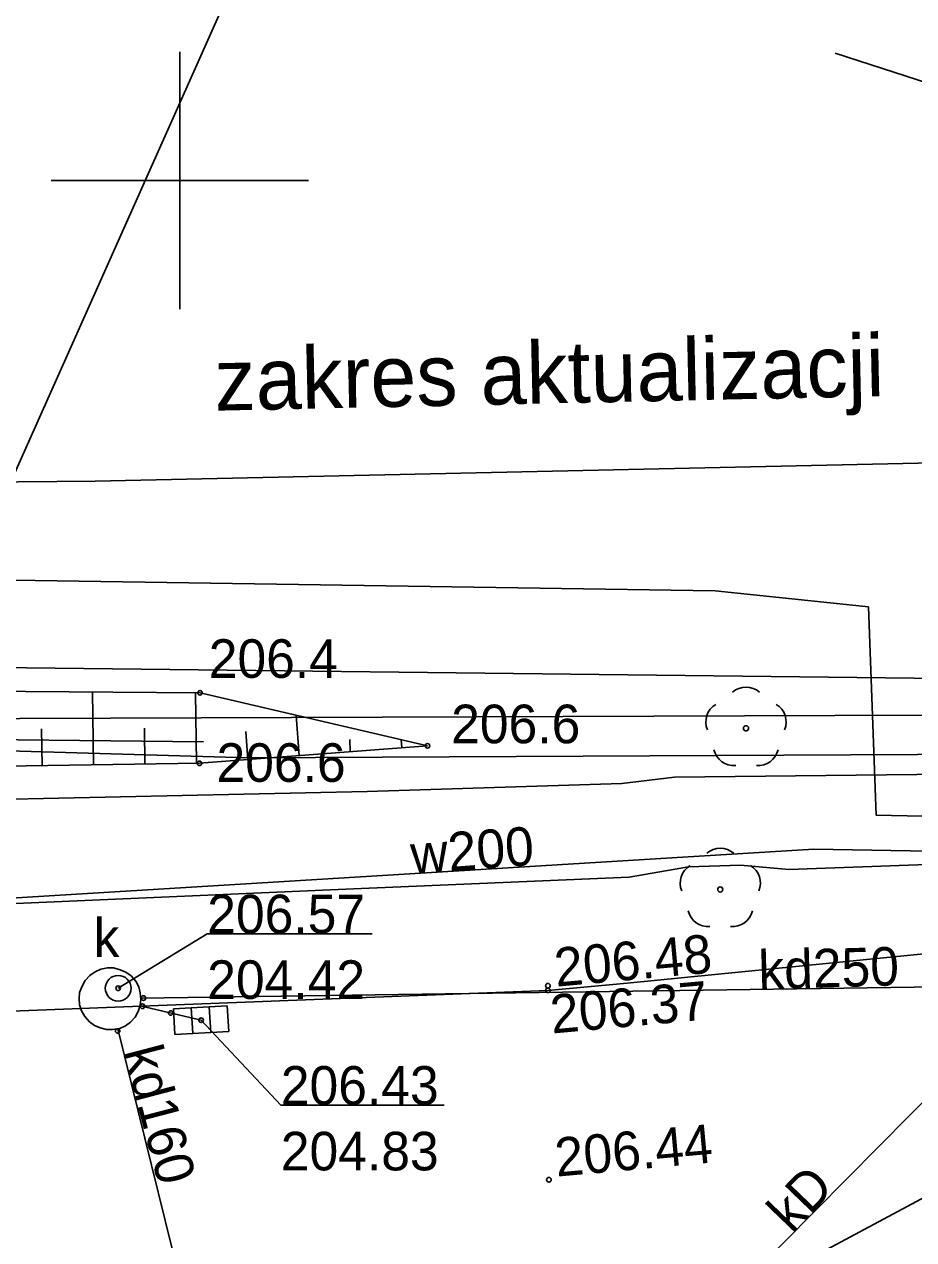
# Model space of a CAD drawing. Extents: x 6512606 to 6513347, y 6022524 to 6022728.
# Drawn here: x 6512746.98 to 6512764.26, y 6022679.43 to 6022703.04 of the extents above; entities that cross this region are included whole.
import ezdxf

# ---------------------------------------------------------------- set-up
doc = ezdxf.new("R2010")
doc.units = 0
for name, color, linetype in [('218-kontur użytku gruntowego', 7, 'Continuous'), ('219-działka ewidencyjna', 7, 'Continuous'), ('4', 7, 'Continuous'), ('820-Skarpa nieumocniona', 7, 'Continuous'), ('823-Szczyt skarpy nieumocninej', 7, 'Continuous'), ('824-Podnóże skarpy nieumocninej', 7, 'Continuous'), ('903-Żywopłot', 7, 'Continuous'), ('996-Tekst dodatkowy mały', 7, 'Continuous'), ('chodnik (powierzchnia)', 7, 'Continuous'), ('Default', 7, 'Continuous'), ('drzewo liściaste (punkt)', 7, 'Continuous'), ('jezdnia (powierzchnia)', 7, 'Continuous'), ('komora podziemna - przewód kanalizacyjny (powierzchnia)', 7, 'Continuous'), ('kratka ściekowa (punkt)', 7, 'Continuous'), ('krawężnik (linia)', 7, 'Continuous'), ('maxp_opisy', 7, 'Continuous'), ('Obszar opracowania', 7, 'Continuous'), ('przewód elektroenergetyczny niskiego napięcia (linia)', 7, 'Continuous'), ('przewód gazowy (linia)', 7, 'Continuous'), ('przewód kanalizacyjny (linia)', 7, 'Continuous'), ('przewód kanalizacyjny (linia)-Atr1', 7, 'Continuous'), ('przewód telekomunikacyjny (linia)', 7, 'Continuous'), ('przewód wodociągowy (linia)', 7, 'Continuous'), ('przewód wodociągowy (linia)-Atr1', 7, 'Continuous'), ('punkt o określonej wysokości (sieć kanalizacyjna)', 7, 'Continuous'), ('punkt o określonej wysokości (sieć kanalizacyjna)-Atr2', 7, 'Continuous'), ('punkt o określonej wysokości (sieć kanalizacyjna)-Atr3', 7, 'Continuous'), ('punkt wysokościowy naturalny', 7, 'Continuous'), ('punkt wysokościowy naturalny-Atr2', 7, 'Continuous'), ('punkt wysokościowy sztuczny', 7, 'Continuous'), ('punkt wysokościowy sztuczny-Atr2', 7, 'Continuous'), ('właz okrągły - siec kanalizacyjna (punkt)', 7, 'Continuous'), ('właz okrągły - siec kanalizacyjna (punkt)-Atr17', 7, 'Continuous')]:
    doc.layers.add(name, color=color, linetype=linetype)

# ---------------------------------------------------------------- blocks, each defined once
blk = doc.blocks.new('PW01')
at = {"layer": 'Default'}
blk.add_circle((0, 0), 0.45, dxfattribs=at)
blk = doc.blocks.new('OP021')
at = {"layer": 'Default'}
blk.add_circle((0, 0), 0.5, dxfattribs=at)
for centre, start, end in [((0, 4), 49.272, 130.728), ((-3.8, 1.24), 121.308, 202.548), ((3.8, 1.24), 337.452, 58.692), ((-2.35, -3.24), 193.221, 274.871), ((2.35, -3.24), 265.129, 346.779)]:
    blk.add_arc(centre, 4, start, end, dxfattribs=at)
blk = doc.blocks.new('US22')
at = {"layer": 'Default'}
blk.add_circle((0, 0), 2.5, dxfattribs=at)
blk = doc.blocks.new('US05')
at = {"layer": 'Default'}
for p, q in [((-5.25, -2.5), (-5.25, 2.5)), ((-5.25, 2.5), (-1.75, 2.5)), ((-1.75, -2.5), (-1.75, 2.5)), ((-1.75, 2.5), (1.75, 2.5)), ((1.75, -2.5), (1.75, 2.5)), ((1.75, 2.5), (5.25, 2.5)), ((5.25, -2.5), (5.25, 2.5)), ((-5.25, -2.5), (-1.75, -2.5)), ((-1.75, -2.5), (1.75, -2.5)), ((1.75, -2.5), (5.25, -2.5))]:
    blk.add_line(p, q, dxfattribs=at)
blk = doc.blocks.new('PW02')
at = {"layer": 'Default'}
blk.add_circle((0, 0), 0.45, dxfattribs=at)

msp = doc.modelspace()

# ---------------------------------------------------------------- linework, layer by layer
at = {"layer": '218-kontur użytku gruntowego'}
for points in [[(6512706.4, 6022691.01), (6512787.08, 6022690.07)], [(6512787.08, 6022690.07), (6512706.4, 6022691.01)]]:
    msp.add_lwpolyline(points, dxfattribs=at)
at = {"layer": '219-działka ewidencyjna'}
msp.add_lwpolyline([(6512706.4, 6022691.01), (6512787.08, 6022690.07)], dxfattribs=at)
at = {"layer": '4'}
msp.add_lwpolyline([(6512706.4, 6022691.01), (6512787.08, 6022690.07)], dxfattribs=at)
at = {"layer": '820-Skarpa nieumocniona'}
for p, q in [((6512748.32, 6022688.65), (6512748.3, 6022690.07)), ((6512750.32, 6022688.68), (6512750.3, 6022690.05)), ((6512752.32, 6022688.83), (6512752.26, 6022689.61)), ((6512749.32, 6022688.66), (6512749.31, 6022689.36)), ((6512747.32, 6022688.63), (6512747.31, 6022689.35)), ((6512751.32, 6022688.75), (6512751.28, 6022689.3)), ((6512753.31, 6022688.91), (6512753.3, 6022689.14)), ((6512754.31, 6022688.98), (6512754.3, 6022689.14))]:
    msp.add_line(p, q, dxfattribs=at)
at = {"layer": '823-Szczyt skarpy nieumocninej'}
msp.add_lwpolyline([(6512754.81, 6022689.02), (6512750.38, 6022688.68), (6512731.85, 6022688.4), (6512721.27, 6022688.58), (6512714.51, 6022690.92)], dxfattribs=at)
at = {"layer": '824-Podnóże skarpy nieumocninej'}
msp.add_lwpolyline([(6512714.51, 6022690.92), (6512719.59, 6022690.77), (6512731.72, 6022690.19), (6512750.39, 6022690.05), (6512754.81, 6022689.02)], dxfattribs=at)
at = {"layer": '903-Żywopłot'}
msp.add_lwpolyline([(6512750.46, 6022689.1), (6512732.44, 6022689.29)], dxfattribs=at)
at = {"layer": 'chodnik (powierzchnia)'}
for points in [[(6512780.55, 6022688.53), (6512780.6, 6022690.36), (6512779.7, 6022699.13), (6512765.93, 6022701.44), (6512762.734, 6022702.478)], [(6512786.39, 6022689.96), (6512786.43, 6022689.56), (6512785.75, 6022688.59), (6512780.55, 6022688.53), (6512773.92, 6022688.46), (6512772.96, 6022688.47), (6512771.38, 6022688.54), (6512759.61, 6022688.41), (6512758.59, 6022688.29), (6512753.64, 6022688.13), (6512742.85, 6022687.9), (6512740.21, 6022687.75), (6512727.76, 6022687.39)], [(6512770.26, 6022685.56), (6512768.81, 6022686.87), (6512761.83, 6022686.62), (6512760.89, 6022686.7), (6512759.88, 6022686.67), (6512758.73, 6022686.47), (6512753.37, 6022686.24), (6512740.24, 6022685.67), (6512727.63, 6022685.27)]]:
    msp.add_lwpolyline(points, dxfattribs=at)
at = {"layer": 'Default'}
for p, q in [((6512750, 6022697.5), (6512750, 6022702.5)), ((6512747.5, 6022700), (6512752.5, 6022700))]:
    msp.add_line(p, q, dxfattribs=at)
at = {"layer": 'jezdnia (powierzchnia)'}
msp.add_lwpolyline([(6512707.74, 6022685), (6512715.41, 6022684.53), (6512729.72, 6022683.88), (6512743.02, 6022683.72), (6512757.15, 6022684.27)], dxfattribs=at)
at = {"layer": 'komora podziemna - przewód kanalizacyjny (powierzchnia)'}
msp.add_lwpolyline([(6512749.24, 6022684.1), (6512749.23, 6022683.98), (6512749.19, 6022683.86), (6512749.13, 6022683.75), (6512749.04, 6022683.65), (6512748.94, 6022683.58), (6512748.83, 6022683.53), (6512748.69, 6022683.51), (6512748.57, 6022683.51), (6512748.45, 6022683.54), (6512748.34, 6022683.59), (6512748.24, 6022683.66), (6512748.15, 6022683.76), (6512748.09, 6022683.87), (6512748.05, 6022683.99), (6512748.04, 6022684.11), (6512748.05, 6022684.23), (6512748.1, 6022684.35), (6512748.16, 6022684.46), (6512748.25, 6022684.56), (6512748.35, 6022684.63), (6512748.46, 6022684.68), (6512748.59, 6022684.71), (6512748.71, 6022684.71), (6512748.84, 6022684.67), (6512748.95, 6022684.62), (6512749.05, 6022684.55), (6512749.14, 6022684.45), (6512749.2, 6022684.34), (6512749.23, 6022684.22)], close=True, dxfattribs=at)
at = {"layer": 'krawężnik (linia)'}
for points in [[(6512757.15, 6022684.27), (6512758.69, 6022684.41), (6512769.83, 6022685.51), (6512772.56, 6022685.82), (6512777.4, 6022686.23), (6512782.53, 6022686.49), (6512786.32, 6022686.51), (6512790.79, 6022686.51)], [(6512757.15, 6022684.27), (6512743.02, 6022683.72), (6512729.72, 6022683.88), (6512715.41, 6022684.53), (6512707.74, 6022685)]]:
    msp.add_lwpolyline(points, dxfattribs=at)
at = {"layer": 'maxp_opisy'}
msp.add_lwpolyline([(6512737.272, 6022673), (6512753.512, 6022709.396), (6512783.273, 6022709.39)], dxfattribs=at)
at = {"layer": 'Obszar opracowania'}
msp.add_lwpolyline([(6512710.98, 6022693.84), (6512748.35, 6022694.16), (6512798.11, 6022695.25), (6512807.47, 6022695.46), (6512809.66, 6022606.87), (6512863.71, 6022622.03), (6512875.13, 6022581.36), (6512755.22, 6022535.25), (6512691.61, 6022568.03), (6512709.16, 6022605.16)], close=True, dxfattribs=at)
at = {"layer": 'przewód elektroenergetyczny niskiego napięcia (linia)'}
for points in [[(6512782.09, 6022689.68), (6512702.887, 6022689.392)], [(6512702.887, 6022689.392), (6512782.09, 6022689.68)], [(6512751.03, 6022673.06), (6512782.09, 6022689.68)], [(6512782.09, 6022689.68), (6512751.03, 6022673.06)]]:
    msp.add_lwpolyline(points, dxfattribs=at)
at = {"layer": 'przewód gazowy (linia)'}
msp.add_lwpolyline([(6512790.27, 6022690.86), (6512788.32, 6022687.6), (6512767.44, 6022687.59), (6512763.53, 6022687.67), (6512763.38, 6022691.72), (6512760.4, 6022692.03), (6512740.79, 6022692.33), (6512723.64, 6022692.06), (6512711.62, 6022691.95), (6512703.17, 6022690.39), (6512702.97, 6022685.4), (6512702.78, 6022684.183)], dxfattribs=at)
at = {"layer": 'przewód kanalizacyjny (linia)'}
for points in [[(6512749.24, 6022684.12), (6512782.48, 6022684.59)], [(6512756.19, 6022673.77), (6512766.65, 6022684.34)], [(6512749.23, 6022683.97), (6512750.41, 6022683.69)], [(6512750.37, 6022677.15), (6512748.79, 6022683.52)]]:
    msp.add_lwpolyline(points, dxfattribs=at)
at = {"layer": 'przewód telekomunikacyjny (linia)'}
msp.add_lwpolyline([(6512786.53, 6022688.5), (6512773.43, 6022688.9), (6512751.33, 6022688.79), (6512741.32, 6022689.08), (6512718.97, 6022688.75), (6512713.12, 6022690.07), (6512711.25, 6022690.1), (6512706.82, 6022689.08), (6512704.98, 6022689.07)], dxfattribs=at)
at = {"layer": 'przewód wodociągowy (linia)'}
msp.add_lwpolyline([(6512777.27, 6022686.75), (6512776.94, 6022686.76), (6512762.32, 6022687.01), (6512742.89, 6022685.83), (6512741.87, 6022684.29)], dxfattribs=at)
at = {"layer": 'punkt o określonej wysokości (sieć kanalizacyjna)-Atr2'}
for points in [[(6512748.8, 6022684.31), (6512750.53, 6022685.37), (6512753.734, 6022685.37)], [(6512750.41, 6022683.69), (6512751.96, 6022682.04), (6512755.133, 6022682.04)]]:
    msp.add_lwpolyline(points, dxfattribs=at)

# ---------------------------------------------------------------- block references
at = {"layer": 'drzewo liściaste (punkt)', "xscale": 0.1, "yscale": 0.10000000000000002}
for p in [(6512761, 6022689.36), (6512760.5, 6022686.23)]:
    msp.add_blockref('OP021', p, dxfattribs=at)
at = {"layer": 'kratka ściekowa (punkt)', "xscale": 0.1, "yscale": 0.09999999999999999, "rotation": 3.2700000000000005}
msp.add_blockref('US05', (6512750.41, 6022683.69), dxfattribs=at)
at = {"layer": 'punkt o określonej wysokości (sieć kanalizacyjna)', "xscale": 0.1, "yscale": 0.10000000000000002}
msp.add_blockref('PW01', (6512748.8, 6022684.31), dxfattribs=at)
at = {"layer": 'punkt o określonej wysokości (sieć kanalizacyjna)'}
for p, xscale, yscale, rotation in [((6512749.29, 6022684.12), 0.1, 0.10000000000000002, 1.62), ((6512749.27, 6022683.96), 0.10000000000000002, 0.1, -12.426), ((6512749.82, 6022683.83), 0.10000000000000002, 0.1, -12.426), ((6512750.41, 6022683.69), 0.1, 0.09999999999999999, 3.2700000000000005), ((6512748.79, 6022683.48), 0.1, 0.10000000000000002, -75.265)]:
    msp.add_blockref('PW01', p, dxfattribs=dict(at, xscale=xscale, yscale=yscale, rotation=rotation))
at = {"layer": 'punkt wysokościowy naturalny', "xscale": 0.1, "yscale": 0.10000000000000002}
for p in [(6512750.39, 6022690.05), (6512754.81, 6022689.02), (6512750.38, 6022688.68)]:
    msp.add_blockref('PW01', p, dxfattribs=at)
at = {"layer": 'punkt wysokościowy sztuczny', "xscale": 0.1, "yscale": 0.10000000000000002}
for p in [(6512757.15, 6022684.36), (6512757.15, 6022684.27), (6512757.17, 6022680.59)]:
    msp.add_blockref('PW02', p, dxfattribs=at)
at = {"layer": 'właz okrągły - siec kanalizacyjna (punkt)', "xscale": 0.1, "yscale": 0.10000000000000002}
msp.add_blockref('US22', (6512748.8, 6022684.31), dxfattribs=at)

# ---------------------------------------------------------------- texts
at = {"layer": '996-Tekst dodatkowy mały'}
msp.add_text('zakres aktualizacji', height=1.2, rotation=1.255, dxfattribs=at).set_placement((6512750.68, 6022695.53))
at = {"layer": 'przewód kanalizacyjny (linia)-Atr1'}
for s, rotation, p in [('kd250', 1.631, (6512761.25, 6022684.29)), ('kd160', 284.715, (6512748.9, 6022683.09)), ('kD', 46.112, (6512761.89, 6022679.53))]:
    msp.add_text(s, height=0.75, rotation=rotation, dxfattribs=at).set_placement(p)
at = {"layer": 'przewód wodociągowy (linia)-Atr1'}
msp.add_text('w200', height=0.75, rotation=4.273, dxfattribs=at).set_placement((6512754.51, 6022686.53))
at = {"layer": 'punkt o określonej wysokości (sieć kanalizacyjna)-Atr2'}
for s, p in [('206.57', (6512750.53, 6022685.378)), ('206.43', (6512751.96, 6022682.048))]:
    msp.add_text(s, height=0.75, dxfattribs=at).set_placement(p)
at = {"layer": 'punkt o określonej wysokości (sieć kanalizacyjna)-Atr3'}
for s, p in [('204.42', (6512750.53, 6022684.103)), ('204.83', (6512751.96, 6022680.772))]:
    msp.add_text(s, height=0.75, dxfattribs=at).set_placement(p)
at = {"layer": 'punkt wysokościowy naturalny-Atr2'}
for s, p in [('206.4', (6512750.56, 6022690.34)), ('206.6', (6512755.27, 6022689.07)), ('206.6', (6512750.71, 6022688.32))]:
    msp.add_text(s, height=0.75, dxfattribs=at).set_placement(p)
at = {"layer": 'punkt wysokościowy sztuczny-Atr2'}
for s, p in [('206.48', (6512757.31, 6022684.34)), ('206.37', (6512757.23, 6022683.43)), ('206.44', (6512757.32, 6022680.65))]:
    msp.add_text(s, height=0.75, rotation=5.194, dxfattribs=at).set_placement(p)
at = {"layer": 'właz okrągły - siec kanalizacyjna (punkt)-Atr17'}
msp.add_text('k', height=0.75, dxfattribs=at).set_placement((6512748.32, 6022684.92))

doc.saveas('drawing.dxf')
